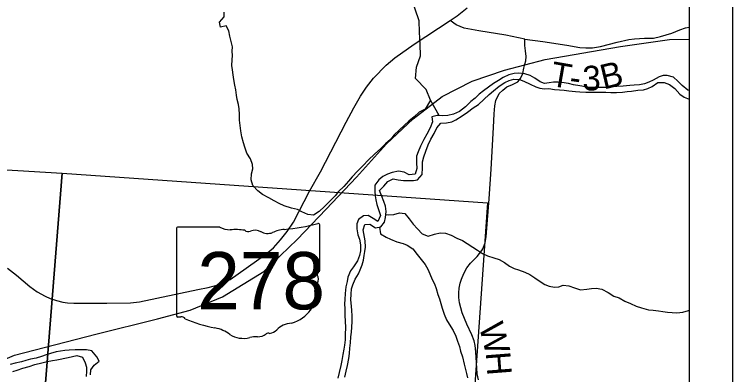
# Model space of a CAD drawing. Extents: x 0 to 34, y 0 to 22.
# Drawn here: x 28.762 to 30.417, y 19.396 to 20.225 of the extents above; entities that cross this region are included whole.
import ezdxf

# ---------------------------------------------------------------- set-up
doc = ezdxf.new("R2010")
doc.units = 0
for name, color, linetype in [('GM_X_County_Road', 7, 'Continuous'), ('GM_X_County_Road_Text', 7, 'Continuous'), ('GM_X_Major_River', 7, 'Continuous'), ('GM_X_Minor_River', 7, 'Continuous'), ('GM_X_Rail_Line', 7, 'Continuous'), ('GM_X_Section', 7, 'Continuous'), ('GM_X_State_Location', 7, 'Continuous'), ('GM_X_State_Route', 7, 'Continuous'), ('GM_X_State_Shield', 7, 'Continuous'), ('GM_X_Township_Road', 7, 'Continuous'), ('GM_X_Township_Road_Text', 7, 'Continuous'), ('SH_Data', 7, 'Continuous')]:
    doc.layers.add(name, color=color, linetype=linetype)

msp = doc.modelspace()

# ---------------------------------------------------------------- linework, layer by layer
at = {"layer": 'GM_X_County_Road'}
msp.add_lwpolyline([(29.831, 19.3846), (29.8284, 19.3983), (29.8255, 19.4487), (29.8237, 19.4635), (29.8211, 19.4743), (29.8161, 19.4877), (29.8047, 19.5122), (29.7939, 19.5387), (29.7875, 19.5614), (29.7859, 19.5735), (29.7859, 19.5847), (29.7866, 19.5953), (29.7894, 19.6065), (29.7919, 19.6162), (29.7976, 19.6294), (29.8046, 19.642), (29.8129, 19.6526), (29.8285, 19.6685), (29.8389, 19.6819), (29.8415, 19.6855), (29.8464, 19.6995), (29.8492, 19.7137), (29.8559, 19.801), (29.8605, 19.8693), (29.8657, 19.9654), (29.8674, 19.9966), (29.869, 20.015), (29.8714, 20.0271), (29.8791, 20.0431), (29.8875, 20.0513), (29.8969, 20.0588), (29.9094, 20.0642), (29.922, 20.0703), (29.9284, 20.0776), (29.9331, 20.0892), (29.9361, 20.1016), (29.938, 20.111), (29.9402, 20.1188), (29.9411, 20.1286), (29.9399, 20.1415), (29.9378, 20.1537), (29.9381, 20.1683), (29.8945, 20.1778), (29.8321, 20.1875), (29.7984, 20.194), (29.7801, 20.2016), (29.7657, 20.2117)], dxfattribs=at)
at = {"layer": 'GM_X_Major_River'}
for points in [[(29.7205, 20.0283), (29.7109, 20.0522), (29.6859, 20.078), (29.6885, 20.1038), (29.6975, 20.13), (29.6966, 20.1566), (29.6958, 20.1843), (29.695, 20.2105), (29.6854, 20.2374), (29.677, 20.2629), (29.6846, 20.2764)], [(30.2025, 20.0635), (30.1896, 20.0624), (30.1797, 20.0616), (30.1642, 20.0601), (30.1497, 20.0594), (30.1357, 20.0582), (30.1258, 20.0575), (30.1126, 20.0575), (30.1, 20.0568), (30.0875, 20.0575), (30.078, 20.0587), (30.0644, 20.061), (30.0503, 20.0636), (30.0386, 20.0663), (30.0234, 20.069), (30.0139, 20.0694), (30.0041, 20.0697), (29.9938, 20.0679), (29.9832, 20.0667), (29.9733, 20.0702), (29.9608, 20.0785), (29.9506, 20.0846), (29.9384, 20.0888), (29.9236, 20.0899), (29.9138, 20.0896), (29.9009, 20.0865), (29.888, 20.0801), (29.8777, 20.0733), (29.8659, 20.0665), (29.8542, 20.0577), (29.8428, 20.0498), (29.8329, 20.0418), (29.8234, 20.0323), (29.8139, 20.0248), (29.8014, 20.0126), (29.7874, 20.0016), (29.7737, 19.9956), (29.7608, 19.9929), (29.7479, 19.9918), (29.741, 19.9925)], [(30.3167, 20.0504), (30.3133, 20.0512), (30.3008, 20.0615), (30.2901, 20.0718), (30.2803, 20.0809), (30.2662, 20.0851), (30.2568, 20.0851), (30.2473, 20.082), (30.234, 20.0741), (30.2237, 20.0692), (30.2139, 20.0658), (30.2025, 20.0635)], [(29.5294, 19.4173), (29.5325, 19.4332), (29.534, 19.445), (29.5351, 19.4572), (29.5363, 19.4697), (29.5374, 19.483), (29.5386, 19.494), (29.5397, 19.5054), (29.5405, 19.5186), (29.5401, 19.5312), (29.5393, 19.5441), (29.5386, 19.554), (29.5375, 19.5684), (29.5379, 19.5813), (29.539, 19.5934), (29.542, 19.6033), (29.5474, 19.6158), (29.5546, 19.628), (29.5591, 19.6378), (29.5637, 19.6492), (29.5664, 19.6595), (29.5683, 19.6701), (29.5698, 19.6796), (29.5709, 19.6898), (29.5702, 19.7042), (29.566, 19.7293), (29.5698, 19.7418), (29.5808, 19.7422), (29.5937, 19.7342), (29.6066, 19.7361), (29.6146, 19.7475), (29.6169, 19.7581), (29.6184, 19.7714), (29.6173, 19.7843), (29.6131, 19.7949), (29.6078, 19.8082), (29.6032, 19.8204), (29.6131, 19.8298), (29.6222, 19.8408), (29.6351, 19.8473), (29.6465, 19.845), (29.6586, 19.8431), (29.6685, 19.8431), (29.6814, 19.8434), (29.6909, 19.8446), (29.7019, 19.8571), (29.7027, 19.8726), (29.7023, 19.8859), (29.7054, 19.8977), (29.7099, 19.9106), (29.7156, 19.925), (29.7217, 19.9383), (29.7289, 19.9512), (29.7357, 19.9641), (29.7449, 19.9747), (29.7578, 19.9758), (29.7699, 19.9785), (29.7794, 19.9827), (29.7934, 19.9921), (29.8056, 20.0005), (29.8189, 20.0107), (29.8314, 20.0183), (29.8439, 20.0297), (29.8561, 20.0414), (29.8655, 20.0494), (29.8788, 20.06), (29.8917, 20.0683), (29.9016, 20.0736), (29.9126, 20.0763), (29.9259, 20.0755), (29.9354, 20.0721), (29.9502, 20.0652), (29.9634, 20.0588), (29.9729, 20.0557), (29.9836, 20.0542), (29.9934, 20.0546), (30.0067, 20.0527), (30.0177, 20.0515), (30.0283, 20.0507), (30.0397, 20.0496), (30.0545, 20.0481), (30.0644, 20.0469), (30.0788, 20.0461), (30.1243, 20.0461), (30.1365, 20.0457), (30.149, 20.0457), (30.163, 20.0464), (30.1736, 20.0476), (30.1839, 20.0487), (30.1983, 20.051), (30.2112, 20.0521), (30.2215, 20.0547), (30.2313, 20.0597), (30.2446, 20.0688), (30.2586, 20.0687), (30.2712, 20.0642), (30.2837, 20.0551), (30.2954, 20.0418), (30.3053, 20.0349), (30.3167, 20.0304)], [(29.741, 19.9925), (29.7205, 20.0283)], [(29.741, 19.9925), (29.7361, 19.9929), (29.7236, 19.9899), (29.7255, 19.9778), (29.7202, 19.9641), (29.7122, 19.9501), (29.7057, 19.9372), (29.6978, 19.9224), (29.6921, 19.9087), (29.6887, 19.8989), (29.6883, 19.884), (29.689, 19.8708), (29.6852, 19.8579), (29.6719, 19.856), (29.6598, 19.8621), (29.6469, 19.8647), (29.6325, 19.8613), (29.6215, 19.8575), (29.6112, 19.8526), (29.6014, 19.8447), (29.5922, 19.8321), (29.5926, 19.8181), (29.5934, 19.8078), (29.5945, 19.7984), (29.5972, 19.7881), (29.6017, 19.7741), (29.6055, 19.7627), (29.5994, 19.749), (29.5888, 19.7558), (29.577, 19.7627), (29.5668, 19.7616), (29.5546, 19.7532), (29.5512, 19.7434), (29.5512, 19.7316), (29.5535, 19.7183), (29.5569, 19.7077), (29.5599, 19.6948), (29.5599, 19.6811), (29.5576, 19.6705), (29.5523, 19.6579), (29.5436, 19.6447), (29.5364, 19.6352), (29.5307, 19.6204), (29.5288, 19.6109), (29.5257, 19.598), (29.5242, 19.5828), (29.5234, 19.5695), (29.523, 19.5593), (29.5238, 19.5475), (29.5238, 19.5323), (29.5245, 19.519), (29.5249, 19.505), (29.5245, 19.4883), (29.5241, 19.4761), (29.523, 19.4644), (29.5215, 19.4549), (29.5192, 19.4424), (29.5165, 19.4291), (29.5142, 19.4169), (29.5104, 19.4014), (29.507, 19.3881)], [(28.9379, 19.3955), (28.9386, 19.4076), (28.9459, 19.4179), (28.9576, 19.427), (28.9523, 19.4372), (28.9409, 19.4509), (28.9284, 19.4536), (28.9163, 19.4536), (28.9022, 19.4532), (28.8886, 19.4525), (28.8783, 19.4517), (28.8685, 19.4506), (28.8586, 19.4487), (28.8453, 19.4445), (28.8355, 19.4415), (28.8248, 19.4381), (28.8123, 19.434), (28.7994, 19.4317), (28.7888, 19.429), (28.7785, 19.426), (28.7645, 19.4226), (28.7523, 19.4196)], [(28.7584, 19.4033), (28.7687, 19.4063), (28.7819, 19.4108), (28.7967, 19.415), (28.8093, 19.4192), (28.8252, 19.4233), (28.8381, 19.4263), (28.8499, 19.4286), (28.8601, 19.4305), (28.8859, 19.4358), (28.8962, 19.4377), (28.9064, 19.4399), (28.9193, 19.4365), (28.9257, 19.4236), (28.9284, 19.4137), (28.9288, 19.4042), (28.9276, 19.3921)], [(29.5233, 19.3904), (29.5264, 19.4044), (29.5294, 19.4173)]]:
    msp.add_lwpolyline(points, dxfattribs=at)
at = {"layer": 'GM_X_Minor_River'}
for points in [[(29.7205, 20.0283), (29.7082, 20.0072), (29.695, 20.0004), (29.6829, 19.9898), (29.6708, 19.9799), (29.6609, 19.9708), (29.6484, 19.9591), (29.6371, 19.9484), (29.6288, 19.9378), (29.6174, 19.9272), (29.6061, 19.9169), (29.5921, 19.9037), (29.5781, 19.8908), (29.5652, 19.8771), (29.5524, 19.8646), (29.5406, 19.8513), (29.5319, 19.8418), (29.5214, 19.8293), (29.5092, 19.8175), (29.5009, 19.8077), (29.4892, 19.7952), (29.4767, 19.7834), (29.4646, 19.7716), (29.4514, 19.7633), (29.4381, 19.7652), (29.4245, 19.7709), (29.4142, 19.7762), (29.4006, 19.7792), (29.3839, 19.7845), (29.3722, 19.7902), (29.3608, 19.7962), (29.3483, 19.8031), (29.3339, 19.8106), (29.3229, 19.8194), (29.3116, 19.8319), (29.3074, 19.8444), (29.3085, 19.8588), (29.3112, 19.8702), (29.3108, 19.8796), (29.3058, 19.8933), (29.2975, 19.9062), (29.2929, 19.9198), (29.2903, 19.9301), (29.2865, 19.9437), (29.2842, 19.9574), (29.2823, 19.9695), (29.2807, 19.982), (29.2807, 19.9953), (29.2803, 20.0078), (29.2784, 20.018), (29.2758, 20.0298), (29.2739, 20.0393), (29.272, 20.0518), (29.27, 20.0628), (29.2678, 20.0757), (29.2662, 20.0867), (29.2647, 20.098), (29.2632, 20.1079), (29.2639, 20.1212), (29.2647, 20.1306), (29.2639, 20.1409), (29.2647, 20.1507), (29.262, 20.1633), (29.2589, 20.175), (29.2559, 20.1875), (29.2498, 20.1993), (29.2373, 20.1962), (29.2351, 20.2076), (29.2456, 20.2201), (29.2456, 20.2308)], [(29.6176, 19.7649), (29.624, 19.7641), (29.6362, 19.7645), (29.6494, 19.7683), (29.6615, 19.7668), (29.6718, 19.7551), (29.6805, 19.7425), (29.6907, 19.7316), (29.7017, 19.7206), (29.7157, 19.7149), (29.7301, 19.7198), (29.743, 19.7225), (29.7551, 19.7221), (29.7687, 19.7172), (29.7812, 19.7104), (29.7941, 19.7047), (29.8051, 19.6982), (29.8184, 19.6895), (29.829, 19.6827), (29.8404, 19.6747), (29.8521, 19.6694), (29.8669, 19.6649), (29.8786, 19.6611), (29.8911, 19.6543), (29.9029, 19.646), (29.9131, 19.6407), (29.9237, 19.6372), (29.9381, 19.6319), (29.9495, 19.627), (29.9608, 19.6194), (29.9711, 19.6119), (29.9843, 19.6039), (29.9942, 19.6001), (30.0063, 19.5975), (30.0161, 19.5986), (30.0267, 19.602), (30.0392, 19.6009), (30.0525, 19.5964), (30.0665, 19.5918), (30.0805, 19.5926), (30.0919, 19.5945), (30.1025, 19.5956), (30.1157, 19.593), (30.1297, 19.585), (30.143, 19.5767), (30.1555, 19.5729), (30.168, 19.5657), (30.1816, 19.5596), (30.1941, 19.5536), (30.2066, 19.5498), (30.2229, 19.5456), (30.2339, 19.5449), (30.246, 19.543), (30.2559, 19.5418), (30.2669, 19.5403), (30.2771, 19.5392), (30.2881, 19.5388), (30.3021, 19.5403), (30.3153, 19.5438), (30.3167, 19.5445)], [(29.6031, 19.7356), (29.6059, 19.7205), (29.6184, 19.7126), (29.6283, 19.7084), (29.643, 19.702), (29.6578, 19.6978), (29.6673, 19.694), (29.6802, 19.686), (29.6904, 19.6724), (29.7086, 19.6497), (29.7143, 19.639), (29.7189, 19.6284), (29.7249, 19.6155), (29.7299, 19.6053), (29.7337, 19.5947), (29.7375, 19.581), (29.7416, 19.5704), (29.7447, 19.5602), (29.7473, 19.5496), (29.7523, 19.5355), (29.7576, 19.5223), (29.7637, 19.5124), (29.7731, 19.498), (29.7792, 19.4847), (29.783, 19.473), (29.7872, 19.4609), (29.7902, 19.4502), (29.7944, 19.437), (29.7982, 19.4203), (29.8005, 19.4108), (29.8035, 19.3987), (29.8062, 19.3892)]]:
    msp.add_lwpolyline(points, dxfattribs=at)
at = {"layer": 'GM_X_Rail_Line'}
msp.add_lwpolyline([(28.6648, 19.3994), (28.7625, 19.4407), (28.9501, 19.4892), (29.0923, 19.5244), (29.1671, 19.545), (29.242, 19.5754), (29.3368, 19.634), (29.414, 19.7075), (29.4806, 19.7769), (29.5501, 19.8507), (29.6195, 19.9273), (29.681, 19.9848), (29.748, 20.0363), (29.8164, 20.0718), (29.8913, 20.0967), (29.9848, 20.1214), (30.1586, 20.1515), (30.2714, 20.1673), (30.3167, 20.1686)], dxfattribs=at)
at = {"layer": 'GM_X_Section'}
for points in [[(27.875, 19.9199), (28.8721, 19.8598), (28.7909, 18.8364), (27.8204, 18.905)], [(29.8523, 19.7915), (29.781, 18.7691), (28.7909, 18.8364), (28.8721, 19.8598)]]:
    msp.add_lwpolyline(points, close=True, dxfattribs=at)
at = {"layer": 'GM_X_State_Route'}
msp.add_lwpolyline([(28.7462, 19.6413), (28.7673, 19.625), (28.7982, 19.5993), (28.8147, 19.5871), (28.8334, 19.5767), (28.845, 19.5715), (28.8597, 19.5669), (28.8741, 19.5629), (28.8848, 19.5617), (28.8995, 19.5605), (28.9145, 19.5605), (28.9753, 19.5608), (29.0298, 19.5617), (29.0506, 19.5639), (29.1849, 19.592), (29.2087, 19.5966), (29.232, 19.6027), (29.2595, 19.6153), (29.3384, 19.6709), (29.3595, 19.6881), (29.3751, 19.7064), (29.3904, 19.7257), (29.4051, 19.7474), (29.4418, 19.8182), (29.4672, 19.863), (29.5266, 19.9776), (29.544, 20.0105), (29.5599, 20.0372), (29.573, 20.0576), (29.5892, 20.079), (29.6183, 20.1083), (29.6385, 20.1255), (29.6834, 20.1567), (29.7657, 20.2117), (29.7818, 20.2222), (29.8054, 20.2404)], dxfattribs=at)
at = {"layer": 'GM_X_State_Shield'}
for p, q in [((29.4656, 19.6362), (29.4656, 19.7409)), ((29.136, 19.7325), (29.136, 19.5324)), ((29.2358, 19.7359), (29.1393, 19.7359)), ((29.4656, 19.6362), (29.4656, 19.6362))]:
    msp.add_line(p, q, dxfattribs=at)
for centre, major_axis, start_param, end_param in [((29.3482, 20.0088), (0.3495, 0), 4.814394, 5.042369), ((29.4619, 19.7413), (0.00367, 0), 6.141152, 7.989035), ((29.1398, 19.7329), (0.00382, 0), 1.712693, 3.28349), ((29.2588, 19.7592), (0.037, 0), 4.042523, 4.731795), ((29.271, 19.6236), (0.133, 0), 1.404758, 1.657858), ((29.3012, 19.734), (0.0107, 0), 3.836095, 5.185415), ((29.3169, 19.7108), (0.0222, 0), 0.950623, 2.079405), ((29.3456, 19.7426), (0.0267, 0), 4.081561, 5.145723), ((29.3928, 19.6748), (0.0703, 0), 1.699011, 2.107814), ((29.4647, 19.6285), (0.00568, 0), 1.883978, 3.671073), ((29.4286, 19.6153), (0.0341, 0), 5.934695, 6.695948), ((29.4617, 19.6358), (0.00393, 0), 5.05454, 6.418171), ((29.4787, 19.5924), (0.0248, 0), 2.387724, 3.262537), ((29.3678, 19.5791), (0.0874, 0), 5.101752, 6.440018), ((29.1398, 19.5319), (0.00385, 0), 3.00124, 4.508301), ((29.1404, 19.5524), (0.0294, 0), 4.665946, 4.897461), ((29.1464, 19.5208), (0.0106, 0), 0.519207, 1.627899), ((29.2802, 19.7006), (0.2524, 0), 4.195997, 4.488961), ((29.4046, 19.4762), (0.0479, 0), 1.647645, 2.488434), ((29.205, 19.4425), (0.079, 0), 0.823519, 1.323587), ((29.2904, 19.5198), (0.0501, 0), 4.026481, 4.996735), ((29.323, 19.5048), (0.0267, 0), 4.691044, 5.507374), ((29.3472, 19.4855), (0.00752, 0), 1.147584, 2.315152), ((29.344, 19.513), (0.0282, 0), 4.937069, 5.64225), ((29.3194, 19.4506), (0.0412, 0), 1.495662, 1.94098)]:
    msp.add_ellipse(centre, major_axis=major_axis, ratio=0.8, start_param=start_param, end_param=end_param, dxfattribs=at)
at = {"layer": 'GM_X_Township_Road'}
msp.add_lwpolyline([(29.9381, 20.1683), (29.9798, 20.1627), (30.0345, 20.1544), (30.0644, 20.149), (30.0785, 20.1481), (30.094, 20.1481), (30.1127, 20.1519), (30.1508, 20.1615), (30.1776, 20.1674), (30.1909, 20.169), (30.2137, 20.1704), (30.2213, 20.1706), (30.2346, 20.1711), (30.2503, 20.1749), (30.2769, 20.1824), (30.2947, 20.1896), (30.3084, 20.1943), (30.3167, 20.1962)], dxfattribs=at)
at = {"layer": 'SH_Data'}
for points in [[(23.4167, 21), (30.4167, 21), (30.4167, 14), (23.4167, 14)], [(23.5167, 20.9), (30.3167, 20.9), (30.3167, 14.1), (23.5167, 14.1)]]:
    msp.add_lwpolyline(points, close=True, dxfattribs=at)

# ---------------------------------------------------------------- texts
at = {"layer": 'GM_X_County_Road_Text'}
for s, rotation, p in [('W', 284.2912, (29.8319, 19.5082)), ('H', 274.4778, (29.8477, 19.447))]:
    msp.add_text(s, height=0.0568, rotation=rotation, dxfattribs=at).set_placement(p)
at = {"layer": 'GM_X_State_Location'}
msp.add_text('278', height=0.000189, rotation=0, dxfattribs=at).set_placement((29.2302, 19.6053))
for s in ['s', 'r']:
    msp.add_text(s, height=0.000189, dxfattribs=at).set_placement((29.2971, 19.6191))
at = {"layer": 'GM_X_State_Shield'}
msp.add_text('278', height=0.13184, dxfattribs=at).set_placement((29.1836, 19.5465))
at = {"layer": 'GM_X_Township_Road_Text'}
for s, rotation, p in [('B', 13.4814, (30.1194, 20.0523)), ('T', 350.0938, (29.9944, 20.0615)), ('3', 0.8205, (30.0709, 20.0501)), ('-', 352.2641, (30.0385, 20.0538))]:
    msp.add_text(s, height=0.0568, rotation=rotation, dxfattribs=at).set_placement(p)

doc.saveas('drawing.dxf')
